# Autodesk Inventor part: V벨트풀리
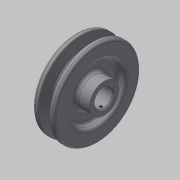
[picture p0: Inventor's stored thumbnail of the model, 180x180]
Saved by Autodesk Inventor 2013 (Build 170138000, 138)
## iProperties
Created: 2015-11
Part Number: V벨트풀리
Material: 강철, 탄소
Document SubType Name: Modeling
Designer: mduedu
Density: 1 g/cm^3
Author: mduedu
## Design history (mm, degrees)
sketch "스케치1"
  geometry: L1 (-9.5, 0)-(9.5, 0); L2 (0, 0)-(0, 37.7); L3 (-4.825, 37.7)-(-9.5, 37.7); L4 (-9.5, 37.7)-(-9.5, 0); L5 (0, 28.7)-(-2.074, 28.7); L6 (-2.074, 28.7)-(-4.825, 37.7); L7 (4.825, 37.7)-(9.5, 37.7); L8 (9.5, 37.7)-(9.5, 0); L9 (0, 28.7)-(2.074, 28.7); L10 (2.074, 28.7)-(4.825, 37.7); L11 (-9.5, 35)-(9.5, 35); 3 further points
  constraints: 22 end point, 7 point on line, 4 perpendicular, 3 symmetric about line, 1 coincident, 1 horizontal, 1 horizontal alignment, 1 midpoint, 1 vertical
  dimensions: "d0" = 19 distance of L1.start L1.end; "d2" = 75.4 diameter of L2.end L1 (derived); "d3" = 34 deg angle of L10 L6; "d4" = 6.3 distance between parallel lines of L11 L9; "d5" = 2.7 distance between parallel lines of L7 L11; "d6" = 8 distance of point (4, 35) point (-4, 35); "d7" = 70 diameter of L11 L1
revolve "회전1" sketch "스케치1" stored, may be unused: angle "d8" = 90 deg
sketch "스케치2"
  geometry: C1 r 24 at (0, 0); C2 r 13 at (0, 0); 1 further point
  constraints: 2 centre point, 2 coincident
  dimensions: "d9" = 48 diameter of C1; "d10" = 26 diameter of C2
extrude "돌출1" cut sketch "스케치2" distance "d11" = 6; taper "d12" = 0 deg
extrude "돌출3" join sketch "스케치2" distance "d37" = 6; taper "d38" = 0 deg
fillet "모깎기1" dims "d13" = 3
fillet "모깎기2" dims "d14" = 3
fillet "모깎기3" dims "d15" = 1, "d16" = 0.5, "d17" = 2
hole "구멍1" diameter "d20" = 16; stored, may be unused: countersink angle "d24" = 90 deg, drill point angle "d26" = 118 deg; dims "d21" = 6, "d22" = 4, "d23" = 2, "d25" = 8, "d53" = 10, "d54" = 10
sketch "스케치3"
  geometry: L1 (-2.5, 0)-(2.5, 0); L2 (2.5, 0)-(2.5, 10.3); L3 (2.5, 10.3)-(-2.5, 10.3); L4 (-2.5, 10.3)-(-2.5, 0); 2 further points
  constraints: 8 end point, 2 parallel, 1 coincident, 1 horizontal, 1 midpoint, 1 perpendicular
  dimensions: "d27" = 5 distance of L2.end L3.end; "d29" = 10.3 distance of L3.end L1.start
extrude "돌출2" cut sketch "스케치3" stored distance "d30" = 6; taper "d31" = 0 deg
chamfer "모따기1" distance "d32" = 1; stored, may be unused: second distance "d33" = 2, angle "d34" = 45 deg
node "작업 평면1"
sketch "스케치4"
  geometry: L1 (19, -27)-(19, 27) reference; 2 further points
  constraints: 1 horizontal alignment
  dimensions: "d52" = 22 distance from line of L1 point (-3, 0)
hole "구멍2" sketch "스케치4" at (-3, 0) diameter "d42" = 2.459; stored, may be unused: countersink angle "d46" = 90 deg, drill point angle "d48" = 118 deg; dims "d43" = 6, "d44" = 4, "d45" = 2, "d47" = 8
chamfer "모따기3" distance "d58" = 1; stored, may be unused: second distance "d59" = 2, angle "d60" = 45 deg
node "솔리드1"
mirror "대칭1"
